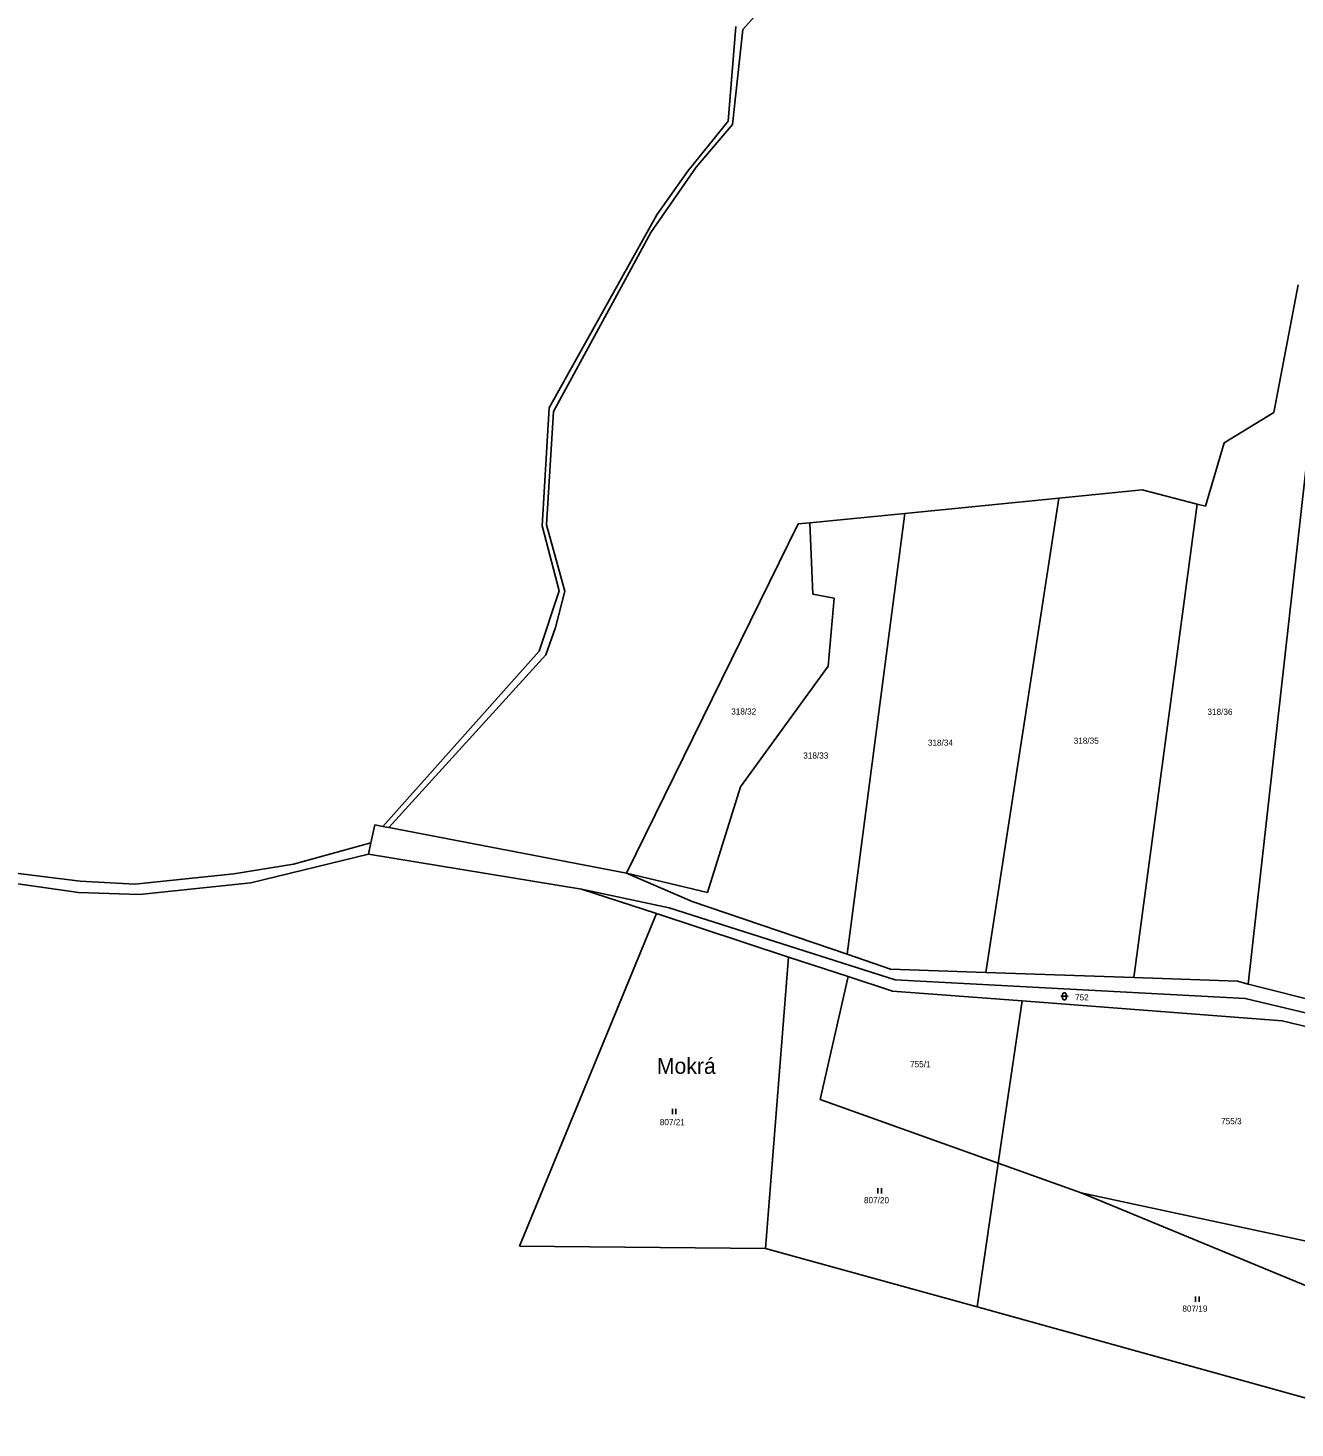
# Model space of a CAD drawing. Extents: x -791032 to -787751, y -1106872 to -1104403.
# Drawn here: x -790680.5 to -790328.9, y -1105502.9 to -1105114.4 of the extents above; entities that cross this region are included whole.
import ezdxf

# ---------------------------------------------------------------- set-up
doc = ezdxf.new("R2010")
doc.units = 0
for name, color, linetype in [('Vrstva 1', 7, 'Continuous'), ('Vrstva 14', 7, 'Continuous'), ('Vrstva 23', 7, 'Continuous'), ('Vrstva 39', 7, 'Continuous'), ('Vrstva 4', 7, 'Continuous')]:
    doc.layers.add(name, color=color, linetype=linetype)

msp = doc.modelspace()

# ---------------------------------------------------------------- linework, layer by layer
at = {"layer": 'Vrstva 1'}
for p, q in [((-790482.13, -1105114.82), (-790453.63, -1105082.57)), ((-790485.01, -1105141.12), (-790482.13, -1105114.82)), ((-790495.07, -1105152.99), (-790485.01, -1105141.12)), ((-790507.72, -1105171.11), (-790495.07, -1105152.99)), ((-790514.78, -1105184.29), (-790507.72, -1105171.11)), ((-790534.67, -1105220.77), (-790514.78, -1105184.29)), ((-790341.9, -1105379.69), (-790320.41, -1105188.35)), ((-790334.77, -1105221.04), (-790328.05, -1105185.69)), ((-790536.66, -1105252.25), (-790534.67, -1105220.77)), ((-790348.58, -1105229.52), (-790334.77, -1105221.04)), ((-790353.75, -1105247.09), (-790348.58, -1105229.52)), ((-790394.41, -1105244.84), (-790371.35, -1105242.56)), ((-790371.35, -1105242.56), (-790356.04, -1105246.5)), ((-790437.19, -1105249.07), (-790394.41, -1105244.84)), ((-790414.72, -1105376.46), (-790394.41, -1105244.84)), ((-790373.61, -1105377.92), (-790356.04, -1105246.5)), ((-790356.04, -1105246.5), (-790353.75, -1105247.09)), ((-790463.51, -1105251.67), (-790437.19, -1105249.07)), ((-790453.15, -1105371.44), (-790437.19, -1105249.07)), ((-790531.55, -1105270.65), (-790536.66, -1105252.25)), ((-790514.44, -1105348.96), (-790466.75, -1105251.99)), ((-790466.75, -1105251.99), (-790463.51, -1105251.67)), ((-790463.51, -1105251.67), (-790462.72, -1105271.52)), ((-790534.13, -1105280.73), (-790531.55, -1105270.65)), ((-790456.8, -1105272.59), (-790462.72, -1105271.52)), ((-790458.51, -1105291.5), (-790456.8, -1105272.59)), ((-790536.8, -1105288.37), (-790534.13, -1105280.73)), ((-790580.36, -1105336.29), (-790536.8, -1105288.37)), ((-790482.8, -1105324.94), (-790458.51, -1105291.5)), ((-790491.91, -1105354.28), (-790482.8, -1105324.94)), ((-790580.36, -1105336.29), (-790582.03, -1105335.97)), ((-790514.44, -1105348.96), (-790580.36, -1105336.29)), ((-790586.02, -1105343.61), (-790585.35, -1105340.54)), ((-790618.67, -1105351.65), (-790586.02, -1105343.61)), ((-790586.02, -1105343.61), (-790526.91, -1105353.35)), ((-790710.1, -1105348.01), (-790666.56, -1105354.32)), ((-790649.58, -1105354.85), (-790618.67, -1105351.65)), ((-790496.18, -1105356.83), (-790514.44, -1105348.96)), ((-790514.44, -1105348.96), (-790491.91, -1105354.28)), ((-790666.56, -1105354.32), (-790649.58, -1105354.85)), ((-790526.91, -1105353.35), (-790506.14, -1105360.16)), ((-790526.91, -1105353.35), (-790502.63, -1105358.5)), ((-790502.63, -1105358.5), (-790439.9, -1105378.57)), ((-790453.15, -1105371.44), (-790496.18, -1105356.83)), ((-790544.15, -1105452.42), (-790506.14, -1105360.16)), ((-790506.14, -1105360.16), (-790469.49, -1105372.19)), ((-790441.13, -1105375.52), (-790453.15, -1105371.44)), ((-790469.49, -1105372.19), (-790475.9, -1105453.04)), ((-790469.49, -1105372.19), (-790452.93, -1105377.62)), ((-790414.72, -1105376.46), (-790441.13, -1105375.52)), ((-790452.93, -1105377.62), (-790460.73, -1105411.7)), ((-790440.64, -1105381.66), (-790452.93, -1105377.62)), ((-790439.9, -1105378.57), (-790342.75, -1105383.75)), ((-790373.61, -1105377.92), (-790414.72, -1105376.46)), ((-790344.85, -1105378.94), (-790373.61, -1105377.92)), ((-790341.9, -1105379.69), (-790344.85, -1105378.94)), ((-790440.64, -1105381.66), (-790404.64, -1105384.39)), ((-790299.85, -1105390.33), (-790341.9, -1105379.69)), ((-790404.64, -1105384.39), (-790411.27, -1105429.42)), ((-790404.64, -1105384.39), (-790332.46, -1105389.88)), ((-790342.75, -1105383.75), (-790314.84, -1105390.3)), ((-790332.46, -1105389.88), (-790275.49, -1105403.65)), ((-790460.73, -1105411.7), (-790411.27, -1105429.42)), ((-790411.27, -1105429.42), (-790417.15, -1105469.31)), ((-790411.27, -1105429.42), (-790388.27, -1105437.66)), ((-790388.27, -1105437.66), (-790290.89, -1105458.59)), ((-790388.27, -1105437.66), (-790292.46, -1105477.26)), ((-790475.9, -1105453.04), (-790544.15, -1105452.42)), ((-790417.15, -1105469.31), (-790475.9, -1105453.04)), ((-790295.85, -1105502.9), (-790417.15, -1105469.31))]:
    msp.add_line(p, q, dxfattribs=at)
at = {"layer": 'Vrstva 23'}
for p, q in [((-790393.89, -1105383.1), (-790391.89, -1105383.1)), ((-790393.39, -1105382.5), (-790393.29, -1105382.3)), ((-790393.39, -1105383.7), (-790393.39, -1105382.5)), ((-790393.29, -1105382.3), (-790393.19, -1105382.2)), ((-790393.19, -1105382.2), (-790392.99, -1105382.1)), ((-790392.99, -1105382.1), (-790392.79, -1105382.1)), ((-790392.79, -1105382.1), (-790392.59, -1105382.2)), ((-790392.59, -1105382.2), (-790392.49, -1105382.3)), ((-790392.49, -1105382.3), (-790392.39, -1105382.5)), ((-790392.39, -1105382.5), (-790392.39, -1105383.7)), ((-790393.29, -1105383.9), (-790393.39, -1105383.7)), ((-790393.19, -1105384), (-790393.29, -1105383.9)), ((-790392.99, -1105384.1), (-790393.19, -1105384)), ((-790392.79, -1105384.1), (-790392.99, -1105384.1)), ((-790392.59, -1105384), (-790392.79, -1105384.1)), ((-790392.49, -1105383.9), (-790392.59, -1105384)), ((-790392.39, -1105383.7), (-790392.49, -1105383.9)), ((-790501.7, -1105415.8), (-790501.7, -1105414.3)), ((-790500.7, -1105414.3), (-790500.7, -1105415.8)), ((-790444.66, -1105437.82), (-790444.66, -1105436.32)), ((-790443.66, -1105436.32), (-790443.66, -1105437.82)), ((-790356.51, -1105467.91), (-790356.51, -1105466.41)), ((-790355.51, -1105466.41), (-790355.51, -1105467.91))]:
    msp.add_line(p, q, dxfattribs=at)
at = {"layer": 'Vrstva 4'}
for p, q in [((-790484.09, -1105113.92), (-790486.18, -1105140.21)), ((-790486.18, -1105140.21), (-790497.49, -1105154.15)), ((-790497.49, -1105154.15), (-790506.04, -1105166.25)), ((-790506.04, -1105166.25), (-790535.89, -1105219.81)), ((-790535.89, -1105219.81), (-790537.8, -1105252.52)), ((-790537.8, -1105252.52), (-790533.12, -1105270.55)), ((-790533.12, -1105270.55), (-790538.69, -1105287.28)), ((-790538.69, -1105287.28), (-790582.03, -1105335.97)), ((-790666.11, -1105351.11), (-790798.53, -1105334.91)), ((-790584.25, -1105335.53), (-790585.35, -1105340.54)), ((-790582.03, -1105335.97), (-790584.25, -1105335.53)), ((-790585.35, -1105340.54), (-790606.85, -1105346.45)), ((-790606.85, -1105346.45), (-790623.46, -1105349.13)), ((-790650.85, -1105351.96), (-790666.11, -1105351.11)), ((-790623.46, -1105349.13), (-790650.85, -1105351.96))]:
    msp.add_line(p, q, dxfattribs=at)

# ---------------------------------------------------------------- texts
at = {"layer": 'Vrstva 14'}
for s, p in [('318/32', (-790485.383, -1105304.89)), ('318/36', (-790353.193, -1105304.99)), ('318/34', (-790430.789, -1105313.56)), ('318/35', (-790390.319, -1105313.01)), ('318/33', (-790465.373, -1105317.12)), ('752', (-790389.949, -1105384.24)), ('755/1', (-790435.732, -1105402.79)), ('807/21', (-790505.188, -1105418.86)), ('755/3', (-790349.409, -1105418.61)), ('807/20', (-790448.524, -1105440.52)), ('807/19', (-790360.159, -1105470.61))]:
    msp.add_text(s, height=1.7, dxfattribs=at).set_placement(p)
at = {"layer": 'Vrstva 39'}
msp.add_text('Mokrá', height=4.4, dxfattribs=at).set_placement((-790506.01, -1105404.62))

doc.saveas('drawing.dxf')
